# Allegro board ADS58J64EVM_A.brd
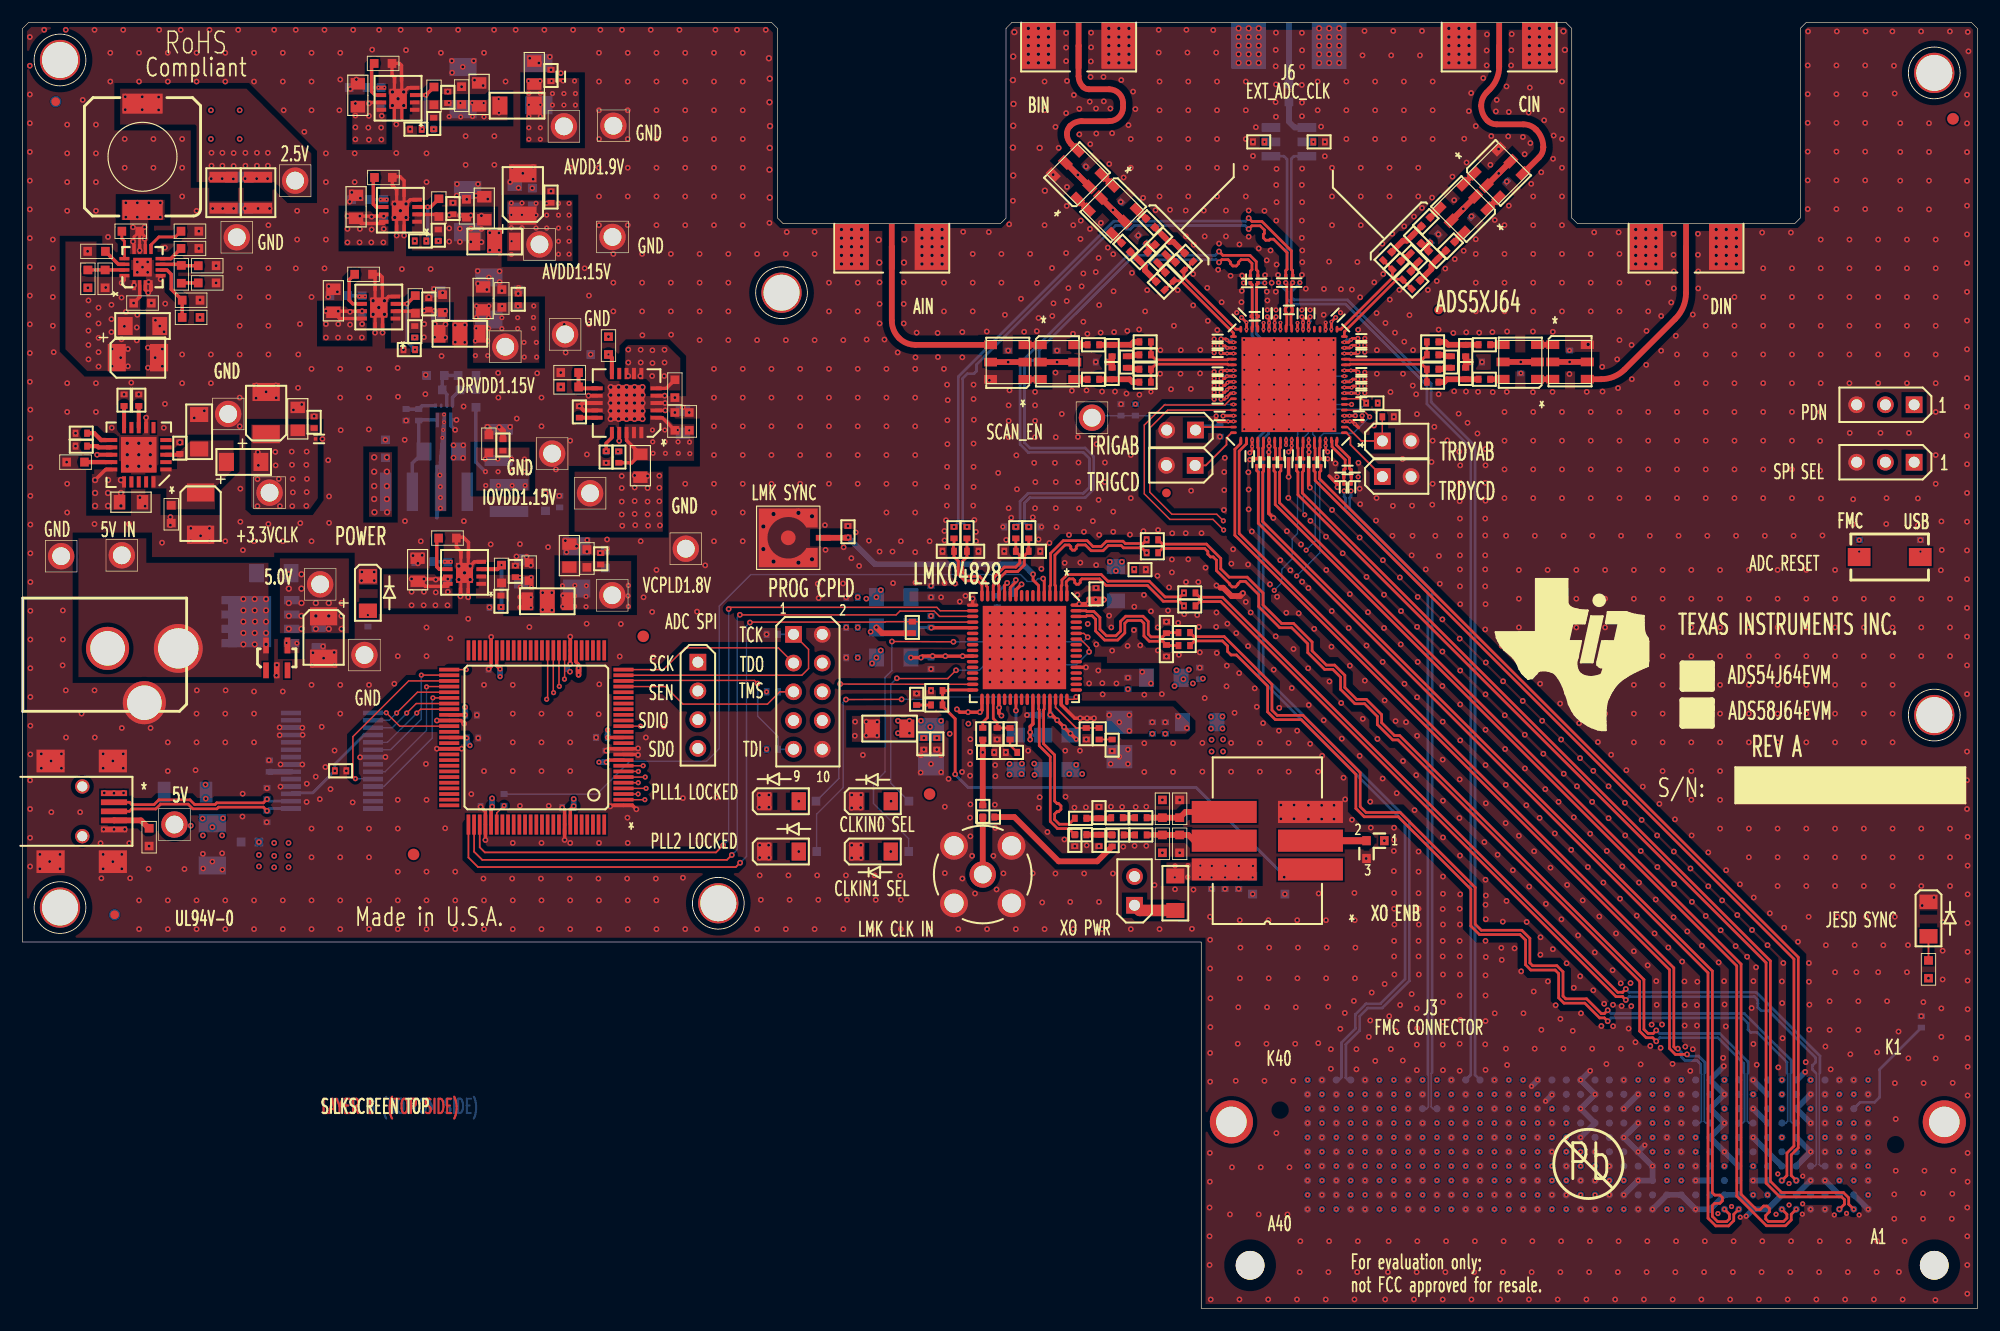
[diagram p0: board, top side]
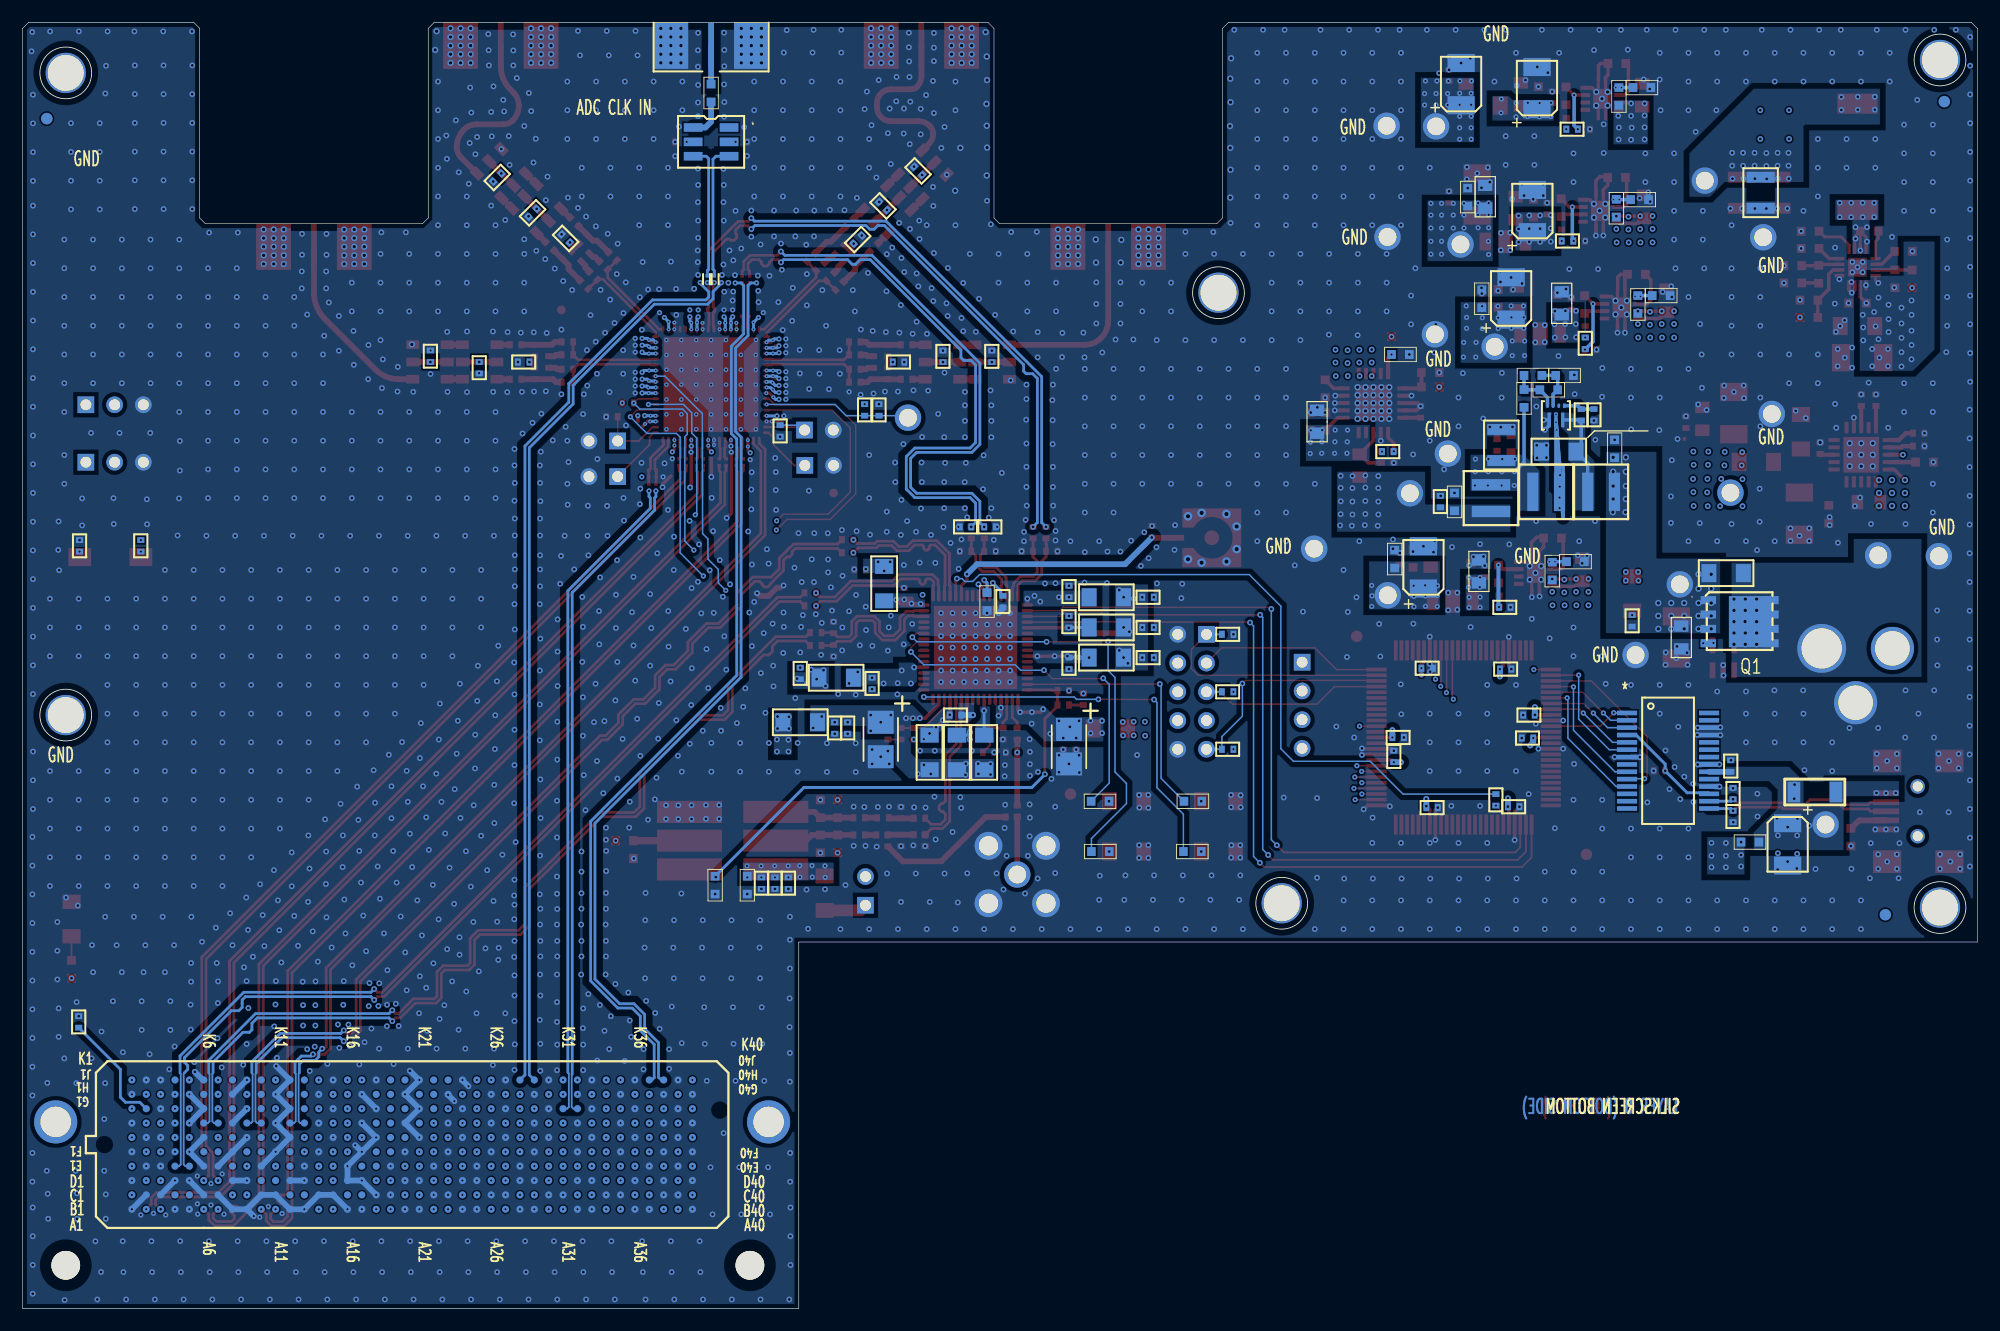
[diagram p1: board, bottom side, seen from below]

Outline 172.72 x 113.66 mm; copper layers: TOP, L2-GND1, L3-PWR1, L4-GND2, L5-GND3, L6-PWR2, L7-GND4, BOTTOM. Coordinates in mm from the lower left corner of the outline.
Outline path: 0,113.16 0.51,113.66 66.19,113.66 66.7,113.16 66.7,96.39 67.21,95.89 86.39,95.89 86.89,96.39 86.89,113.16 87.4,113.66 136.37,113.66 136.88,113.16 136.88,96.39 137.39,95.89 156.57,95.89 157.07,96.39 157.07,113.16 157.58,113.66 172.21,113.66 172.72,113.16 172.72,0 104.14,0 104.14,32.39 0,32.39 0,113.16

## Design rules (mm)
net group ACLK: nets ACLKN ACLKP
net group DIFFPAIR5: nets ACLK_N ACLK_P
net group DIFFPAIR10: nets DDINM DDINP
net group DIFFPAIR20: nets CLKM CLKP
net group DIFFPAIR44: nets SYSREF+ SYSREF-
net group DIFFPAIR45: nets SYSREFM SYSREFP
net group DIFFPAIR56: nets JESD_SYSREFM JESD_SYSREFP
net group DIFFPAIR57: nets JESD_CLKM JESD_CLKP
net group DIFFPAIR58: nets CLK_LAO_0M CLK_LAO_0P
net group DIFFPAIR60: nets OSCIN_N OSCIN_P
net group DIFFPAIR74: nets SYSREF_N SYSREF_P
net group DIFFPAIR77: nets FMC_SYSREF_N FMC_SYSREF_P
net group DIFFPAIR78: nets FPGA_JESD_SYSREFM FPGA_JESD_SYSREFP
net group DIFFPAIR79: nets FPGA_JESD_CLKM FPGA_JESD_CLKP
net group DIFFPAIR80: nets FMC_CLK_N FMC_CLK_P
net group DIFFPAIR81: nets CLKIN1N CLKIN1P
net group DIFFPAIR82: nets CLK_N CLK_P
net group DIFFPAIR83: nets CLKLA_0N CLKLA_0P
net group DIFFPAIR84: nets DAM DAP
net group DIFFPAIR85: nets DBM DBP
net group DIFFPAIR86: nets DB_M DB_P
net group DIFFPAIR87: nets DCM DCP
net group DIFFPAIR88: nets DC_M DC_P
net group DIFFPAIR89: nets DDM DDP
net group DIFFPAIR90: nets SYNCBABM SYNCBABP
net group DIFFPAIR91: nets SYNCBCDM SYNCBCDP
net group DIFFPAIR92: nets DD_M DD_P
net group DP1: nets BBINM BBINP
net group DP2: nets CCINM CCINP
net group DP5: nets DA_M DA_P
net group DP6: nets N18153199 N18153268
net group DP7: nets N19895674 N19895681

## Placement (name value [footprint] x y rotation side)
C2  .1uF  [0402]  95.33 83.66 180 bottom
C3  3.3pF  [0402]  97.54 83.66 90 top
C4  .1uF  [0402]  87.08 84.16 270 bottom
C5  .1uF  [0402]  91.4 84.16 270 bottom
C8  .1uF  [0402]  128.45 83.66 0 bottom
C9  3.3pF  [0402]  126.24 83.66 270 top
C10  .1uF  [0402]  136.69 84.18 270 bottom
C11  .1uF  [0402]  132.37 83.16 90 bottom
C16  .1uF  [0201]  118.29 80.92 0 top
C17  .1uF  [0201]  105.59 80.37 180 top
C18  .1uF  [0201]  105.77 78.89 180 top
C19  .1uF  [0201]  115.32 75.41 270 top
C20  .1uF  [0201]  118.29 85.75 0 top
C21  .1uF  [0201]  118.29 84.53 0 top
C22  .1uF  [0201]  111.86 75.41 270 top
C23  .1uF  [0201]  118.29 85.14 0 top
C24  .1uF  [0201]  118.29 82.14 0 top
C25  .01uF  [0201]  113.77 87.96 90 top
C26  .01uF  [0201]  109.98 87.96 90 top
C27  .1uF  [0201]  109.04 74.8 270 top
C28  .1uF  [0201]  109.65 74.8 270 top
C29  .1uF  [0201]  110.57 74.8 270 top
C30  .1uF  [0201]  111.18 74.8 270 top
C31  .1uF  [0201]  113.18 74.8 270 top
C32  .1uF  [0201]  112.57 74.8 270 top
C33  .1uF  [0201]  114.71 74.8 270 top
C34  .1uF  [0201]  114.1 74.8 270 top
C35  .1uF  [0201]  118.29 81.53 0 top
C36  .1uF  [0201]  113.03 87.96 90 top
C37  .1uF  [0201]  116.23 87.81 45 top
C38  .1uF  [0201]  110.74 87.96 90 top
C39  .1uF  [0201]  105.59 84.48 180 top
C40  .1uF  [0201]  107.49 87.81 135 top
C41  .1uF  [0201]  105.59 80.98 180 top
C43  .01uF  [0603]  111.89 107.44 270 bottom
C47  .1uF  [0201]  112.22 90.98 90 top
C48  .1uF  [0201]  111.61 90.98 90 top
C49  .1uF  [0402]  114.55 103.12 0 top
C50  1uF  [0402]  79.63 49.91 270 top
C51  10uF  [3528]  80.26 49.66 270 bottom
C52  .01uF  [0402]  80.77 49.91 270 top
C53  .1uF  [0201]  118.06 78.92 0 top
C56  .01uF  [0402]  98.73 65.3 0 top
C57  1uF  [0402]  99.82 51.31 270 bottom
C58  10uF  [3528]  96.9 50.29 270 bottom
C59  .01uF  [0402]  100.96 51.31 270 bottom
C60  .1uF  [0402]  80.77 54.61 180 top
C61  .01uF  [0402]  104.01 56.13 90 bottom
C62  .01uF  [0402]  73.28 60.2 180 bottom
C63  .01uF  [0402]  73.28 57.53 180 bottom
C64  .01uF  [0402]  73.28 62.87 180 bottom
C65  .68uF  [0402]  80.77 53.34 180 top
C66  3900pF  [0402]  95.12 50.8 270 top
C67  .1uF  [0402]  103.12 62.1 0 top
C68  .1uF  [0402]  103.12 63.25 0 top
C69  47pF  [0402]  93.98 50.8 270 top
C70  .1uF  [0402]  83.44 68.58 90 top
C71  .1uF  [0402]  82.3 68.58 90 top
C72  .1uF  [0402]  87.76 68.58 90 top
C73  .1uF  [0402]  88.9 68.58 90 top
C74  47uF  [1206]  15.6 77.5 90 top
C75  33uF  [TANT_B]  21.51 79.15 90 top
C76  4.7uF  [TANT_B]  15.72 70.26 270 top
C77  .1uF  [0402]  25.76 78.33 90 top
C78  .01uF  [0201]  26.19 76.86 0 top
C79  .1uF  [0402]  86.11 50.8 90 top
C80  .1uF  [0402]  96.7 43.38 180 top
C81  100pF  [0603]  108.69 37.41 90 bottom
C82  .1uF  [0402]  93.48 43.32 180 top
C83  10uF  [0805]  24.31 78.64 90 top
C84  2200pF  [0402]  107.44 37.59 90 bottom
C85  10pF  [0402]  105.05 37.59 90 bottom
C86  .1uF  [0402]  102.64 58.6 180 top
C87  10uF  [0603]  87.5 62.48 270 bottom
C88  .1uF  [0402]  86.11 62.48 270 bottom
C89  .1uF  [0402]  102.64 59.74 180 top
C90  .1uF  [0402]  106.25 37.59 90 bottom
C91  .1uF  [0402]  21.79 47.95 90 bottom
C92  .1uF  [0402]  93.48 41.87 180 top
C93  47pF  [0402]  21.59 43.48 270 bottom
C94  100pF  [0603]  111.53 37.41 90 bottom
C95  47pF  [0402]  21.59 45.52 90 bottom
C96  22uF  [1210]  19.15 98.63 90 bottom
C97  22uF  [1210]  17.75 98.63 90 top
C98  1uF  [0603]  4.67 74.81 180 top
C99  .1uF  [0402]  28.09 47.52 0 top
C100  1uF  [0402]  94.84 63.17 90 top
C101  1uF  [0402]  97.66 55.25 270 bottom
C102  1uF  [0402]  80.26 57.02 270 bottom
C103  47uF  [TANT_B]  26.59 59.31 270 top
C104  10uF  [0805]  26.16 59.31 270 bottom
C105  10uF  [0805]  29.62 107.24 90 top
C106  .47uF  [0603]  36.35 107.19 90 top
C107  .1uF  [0402]  37.57 107.06 90 top
C108  1uF  [0603]  38.79 107.21 90 top
C109  10uF  [0805]  40.34 107.31 90 top
C110  33uF  [TANT_B]  45.62 108.23 90 bottom
C111  10uF  [0805]  45.21 109.25 90 top
C112  .1uF  [0402]  46.69 108.99 90 top
C113  .01uF  [0201]  47.55 108.89 90 top
C114  .47uF  [0603]  31.85 110.06 0 top
C115  1.0uF  [0603]  57.63 78.41 90 top
C116  .01uF  [0603]  58.9 78.41 90 top
C117  10uF  [0805]  58.34 78.38 90 bottom
C118  10uF  [1206]  10.59 86.84 0 top
C119  4.7uF  [TANT_B]  10.19 84.05 0 top
C120  .1uF  [0603]  10.59 88.87 0 top
C121  .1uF  [0402]  92.97 41.37 90 top
C122  .1uF  [0402]  84.84 50.8 90 top
C123  4.7uF  [TANT_B]  39.32 97 90 bottom
C124  .1uF  [0603]  9.56 95.22 180 top
C125  22uF  [1210]  20.8 98.63 90 top
C126  10uF  [0805]  29.46 97.38 90 top
C127  .1uF  [0402]  38.02 97.23 90 top
C128  1uF  [0603]  39.22 97.26 90 top
C129  .47uF  [0603]  36.78 97.31 90 top
C130  33uF  [TANT_B]  44.2 98.48 90 top
C131  10uF  [0805]  43.48 98.27 90 bottom
C132  1uF  [0603]  45.03 98.25 90 bottom
C133  .1uF  [0402]  46.69 98.25 90 top
C134  .47uF  [0603]  31.88 99.97 0 top
C135  3300pF  [0603]  16.31 92.18 0 top
C136  .01uF  [0603]  14.78 95.22 0 top
C137  .47uF  [0603]  34.7 88.75 90 top
C138  .1uF  [0402]  35.89 88.8 90 top
C139  1uF  [0603]  37.11 88.82 90 top
C140  .1uF  [0402]  94.61 85.18 0 top
C141  .1uF  [0402]  94.61 82.13 0 top
C142  33uF  [TANT_B]  41.2 89.28 90 bottom
C143  10uF  [0805]  40.69 89.28 90 top
C144  3300pF  [0603]  16.31 90.65 0 top
C145  1uF  [0603]  43.79 89.26 90 bottom
C146  .1uF  [0402]  43.79 89.2 90 top
C147  1uF  [0603]  42.34 89.28 90 top
C148  4.7uF  [TANT_B]  38.91 107.87 90 bottom
C149  10uF  [0805]  9.58 71.27 0 top
C150  .1uF  [0402]  13.89 76.05 90 top
C151  1uF  [0603]  13.13 70.21 270 top
C152  .1uF  [0402]  40.97 44.35 0 bottom
C153  .1uF  [0402]  48.18 44.27 0 bottom
C154  .1uF  [0402]  39.62 52.45 180 bottom
C155  .1uF  [0402]  51.18 50.47 0 bottom
C156  .1uF  [0402]  51.56 48.79 270 bottom
C157  .1uF  [0402]  129.16 82.14 180 top
C158  .1uF  [0402]  129.16 85.19 180 top
C160  .1uF  [0201]  105.59 85.09 180 top
C161  .1uF  [0201]  105.59 81.58 180 top
C162  .1uF  [0402]  39.75 50.42 180 bottom
C163  4.7uF  [TANT_B]  16.76 41.02 270 bottom
C164  1uF  [0402]  90.3 52.45 180 bottom
C165  .1uF  [0402]  48.62 56.59 0 bottom
C166  .1uF  [0402]  41.68 56.52 0 bottom
C169  .1uF  [0402]  96.77 41.85 180 top
C170  .1uF  [0201]  108.43 75.33 270 top
C171  .1uF  [0201]  105.59 85.7 180 top
C172  .1uF  [0201]  118.29 82.75 0 top
C173  1uF  [0402]  80.26 60.71 90 bottom
C174  1uF  [0402]  80.26 63.37 90 bottom
C175  .1uF  [0402]  87.25 50.8 90 top
C182  10uF  [0805]  36.73 88.85 90 bottom
C183  .47uF  [0603]  30.12 91.41 0 top
C184  1.0uF  [0603]  50.98 84.33 180 bottom
C185  10uF  [0603]  57.63 81.31 270 top
C190  .1uF  [0201]  109.45 90.65 180 top
C191  .1uF  [0201]  108.18 90.65 0 top
C192  .1uF  [0201]  112.55 90.68 180 top
C193  .1uF  [0201]  111.28 90.68 0 top
C194  DNI  [0603]  32.05 76 90 bottom
C195  10uF  [1206]  36.98 75.74 0 bottom
C196  DNI  [0603]  37.87 81.2 180 bottom
C197  DNI  [0603]  41.2 76.43 90 top
C198  DNI  [0402]  42.44 76.33 90 top
C200  .1uF  [0402]  96.7 97.46 225 bottom
C201  .1uF  [0402]  98.93 94.49 135 bottom
C202  .1uF  [0402]  126.15 93.9 225 top
C203  .1uF  [0402]  123.99 96.06 225 top
C204  .1uF  [0402]  130.78 99.97 135 bottom
C205  .1uF  [0402]  127.66 96.85 135 bottom
C206  .1uF  [0402]  124.74 94.59 45 bottom
C207  3.3pF  [0402]  123 92.91 315 top
C263  10uF  [0805]  40.79 97.26 90 top
C265  .015uF  [0402]  49.2 79.25 90 top
C271  150uF  [1210]  42.06 76.33 90 bottom
C272  DNI  [0603]  46.2 71.3 90 bottom
C273  DNI  [0402]  47.45 71.32 90 bottom
C274  .1uF  [0402]  97.49 93.8 315 top
C275  .1uF  [0402]  99.65 95.95 315 top
C276  3.3pF  [0402]  100.64 92.81 45 top
C277  .1uF  [0402]  93.6 100.56 225 bottom
C278  10uF  [0805]  48.31 66.55 90 top
C279  33uF  [TANT_B]  48.95 65.51 90 bottom
C280  .1uF  [0402]  51.08 66.27 90 top
C281  1uF  [0603]  49.86 66.29 90 top
C282  1uF  [0603]  51.49 66.24 90 bottom
C283  .1uF  [0402]  43.54 65.15 90 top
C284  1uF  [0603]  44.75 65.13 90 top
C285  10uF  [0805]  44.04 65.15 90 bottom
C286  .47uF  [0603]  37.54 68.1 0 top
C287  .47uF  [0603]  42.32 64.92 90 top
C288  10uF  [0805]  27.46 89.08 90 top
C289  10uF  [0805]  34.9 65.3 90 top
C290  .1uF  [0402]  109.22 103.12 180 top
C291  .1uF  [0201]  105.59 82.19 180 top
C292  .1uF  [0201]  105.59 82.8 180 top
D1  LED GREEN  [LED_1206]  168.4 34.42 90 top
D2  LED GREEN  [LED_1206]  30.51 63.2 90 top
D3  LED GREEN  [LED_1206]  67.06 40.39 180 top
D4  LED GREEN  [LED_1206]  75.18 44.83 180 top
D5  LED GREEN  [LED_1206]  75.18 40.39 180 top
D6  LED GREEN  [LED_1206]  67.06 44.83 180 top
F1  FUSE 10A 63V FAST  [1206]  22.2 65 0 bottom
FB1  120 OHM @ 100MHz  [1206]  76.61 51.26 0 top
FB2  120 OHM @ 100MHz  [1206]  104.01 51.82 180 bottom
FB3  120 OHM @ 100MHz  [1206]  87.76 49.15 90 bottom
FB4  120 OHM @ 100MHz  [1206]  92.58 49.15 90 bottom
FB5  120 OHM @ 100MHz  [1206]  76.96 62.87 0 bottom
FB6  120 OHM @ 100MHz  [1206]  76.96 60.2 0 bottom
FB7  120 OHM @ 100MHz  [1206]  76.96 57.53 0 bottom
FB8  120 OHM @ 100MHz  [1206]  100.84 55.75 180 bottom
FB9  120 OHM @ 100MHz  [1206]  96.6 64.07 270 bottom
FB10  1K OHM @ 100MHz  [1806]  14.35 45.64 180 bottom
FB11  120 OHM @ 100MHz  [1206]  90.17 49.15 90 bottom
FB12  120 OHM @ 100MHz  [1206]  101.85 36.7 270 top
FB13  27uF  [1206_BEAD_NFM31P]  41.71 94.31 0 top
FB14  27uF  [1206_BEAD_NFM31P]  38.63 86.16 0 top
FB15  120 OHM @ 100MHz  [1206]  43.69 106.32 0 top
FB16  120 OHM @ 100MHz  [1206]  19.53 74.83 0 top
FB17  27uF  [1206_BEAD_NFM31P]  46.36 62.51 0 top
J1  CONN, SMA, JACK, 50 OHM, EDGE MNT  [SMA_SMEL_DUAL_PSF-S01_250X215]  76.8 95.89 0 top
J3  CON, SMVT, FIELD ARRAY, 400POS, MALE  [CON_SMVT_40X10_SEAM_MTG]  138.3 14.48 0 bottom
J5  CONN, SMA, JACK, 50 OHM, EDGE MNT  [SMA_SMEL_DUAL_PSF-S01_250X215]  146.98 95.89 0 top
J6  CONN, SMA, JACK, 50 OHM, EDGE MNT  [SMA_SMEL_DUAL_PSF-S01_250X215]  111.89 113.66 180 bottom
J10  CONN, SMP, PLUG, 50 OHM, THVT  [SMP_B120]  67.65 68.12 90 top
J12  CONN, SMA, JACK, 50 OHM, THVT  [SMA_THVT_312X312]  84.84 38.35 180 top
J13  CONN, USB MINI AB, SMT  [CON_SMRT_USBMNE20_F]  4.62 43.94 0 top
J14  CONN, JACK, PWR, MINI, R/A, TH  [CON_RAPC722_JACK_THVT_3]  10.63 58.34 270 top
J15  HDR, THVT, HI-TEMP, 5POS  [HDR_THVT_2X5_100_M]  68.12 59.59 0 top
J17  CONN, SMA, JACK, 50 OHM, EDGE MNT  [SMA_SMEL_DUAL_PSF-S01_250X215]  93.31 113.66 0 top
J18  CONN, SMA, JACK, 50 OHM, EDGE MNT  [SMA_SMEL_DUAL_PSF-S01_250X215]  130.47 113.66 0 top
J21  HMTSW-102-07-G-S-.240  [HDR_THVT_1X2_100_M]  103.61 74.52 270 top
J22  HMTSW-102-07-G-S-.240  [HDR_THVT_1X2_100_M]  120.14 73.53 90 top
J23  HMTSW-102-07-G-S-.240  [HDR_THVT_1X2_100_M]  103.63 77.65 270 top
J24  HMTSW-102-07-G-S-.240  [HDR_THVT_1X2_100_M]  120.14 76.68 90 top
J25  HMTSW-104-07-G-S-.240  [HDR_THVT_1X4_100_M]  59.66 57.12 0 top
JP2  HDR, THVT, 2POS  [HDR_THVT_1X2_100_M]  98.25 35.64 180 top
JP3  HDR, THVT, 3POS  [HDR_THVT_1X3_100_M]  167.13 74.8 270 top
JP7  HDR, THVT, 3POS  [HDR_THVT_1X3_100_M]  167.13 79.88 270 top
L1  1.5uH  [IND_SM_MSS1048]  10.59 101.8 0 top
L2  0 OHM  [IND_SM_169X169_XFL4020]  33.25 72.19 0 bottom
L3  0 OHM  [IND_SM_169X169_XFL4020]  42.98 71.63 270 bottom
L4  1.0uH  [IND_SM_169X169_XFL4020]  38.1 72.19 0 bottom
MT1  STANDOFF, FEMALE, 4-40 X 1 3/16", AL  [MFG125_PLATED]  61.47 35.81 0 top
MT2  STANDOFF, FEMALE, 4-40 X 1 3/16", AL  [MFG125_PLATED]  67.06 89.79 0 top
MT3  STANDOFF, FEMALE, 4-40 X 1 3/16", AL  [MFG125_PLATED]  3.3 35.43 0 top
MT4  STANDOFF, FEMALE, 4-40 X 1 3/16", AL  [MFG125_PLATED]  168.91 109.22 0 top
MT5  STANDOFF, FEMALE, 4-40 X 1 3/16", AL  [MFG125_PLATED]  168.91 52.45 0 top
MT6  STANDOFF, FEMALE, 4-40 X 1 3/16", AL  [MFG125_PLATED]  3.3 110.36 0 top
NOREF  -  []  -98.16 -130.05 0 top
NOREF#2  -  []  123 169.4 0 top
NOREF#3  -  []  136.32 11.5 0 top
NOREF#4  -  []  104.14 0 0 top
NOREF#5  -  [unnamed#2]  108.46 3.81 0 top
NOREF#6  -  [unnamed#2]  101.07 72.09 0 top
NOREF#7  -  [unnamed#2]  168.91 3.81 0 top
NOREF#8  -  []  0 113.16 0 top
NOREF#9  -  [unnamed#3]  54.84 59.41 0 top
NOREF#10  -  []  0 32.39 0 top
NOREF#11  -  []  86.89 113.16 0 top
NOREF#12  -  []  -0.51 40.89 0 top
NOREF#13  -  [unnamed#3]  80.14 45.47 270 top
NOREF#14  -  []  104.14 0 90 top
NOREF#15  -  []  138.2 58.34 0 top
NOREF#16  -  [unnamed#3]  34.54 40.13 0 top
NOREF#17  -  []  117.25 3.53 0 top
NOREF#18  -  [unnamed#2]  125.12 88.27 0 top
NOREF#19  -  [unnamed#2]  2.92 106.68 0 top
NOREF#20  -  []  98.29 17.8 0 top
NOREF#21  -  []  423.16 122.94 0 top
NOREF#22  -  [unnamed#2]  8.13 34.8 0 top
NOREF#23  -  []  104.14 0 90 top
NOREF#24  -  []  157.07 113.16 0 top
NOREF#25  -  []  66.7 113.16 0 top
NOREF#26  -  []  147.95 58.73 0 top
NOREF#27  -  []  29.26 33.88 0 top
NOREF#28  -  []  -97.92 -130.3 0 top
NOREF#29  -  []  0 32.39 90 top
NOREF#30  -  []  136.88 113.16 0 top
NOREF#31  -  [unnamed#3]  170.56 105.16 0 top
NOREF#32  -  []  0 32.39 0 top
NOREF#33  -  []  26.92 108.59 0 top
NOREF#34  -  []  146.48 49.43 0 top
NOREF#35  -  [unnamed#3]  8.13 34.8 180 bottom
NOREF#36  -  [unnamed#3]  2.92 106.68 180 bottom
NOREF#37  -  [unnamed#3]  170.59 105.18 180 bottom
Q1  CSD18532Q5  [SON_Q5B_8]  21.01 60.71 180 bottom
R2  4.99  [0402]  99.19 81.88 0 top
R3  24.9  [0402]  96.27 82.64 90 top
R5  24.9  [0402]  96.27 84.68 90 top
R6  4.99  [0402]  99.19 85.44 0 top
R8  4.99  [0402]  124.59 85.44 180 top
R9  24.9  [0402]  127.51 84.68 270 top
R11  24.9  [0402]  127.51 82.64 270 top
R12  4.99  [0402]  124.59 81.88 180 top
R13  0  [0603]  11.18 41.66 90 top
R18  1K  [0402]  162.28 67.41 270 bottom
R19  0  [0402]  98.32 79.43 270 bottom
R20  10K  [0402]  97.05 79.43 90 bottom
R21  240  [0402]  83.95 66.93 0 top
R23  1K  [0402]  119.23 80.04 180 top
R28  0  [0402]  35 78.99 90 bottom
R29  0  [0402]  33.88 78.99 270 bottom
R30  0  [0201]  109.14 90.96 270 top
R31  0  [0201]  108.48 90.96 270 top
R32  162K  [0603]  36.47 82.47 180 bottom
R33  10  [0603]  40.06 80.44 90 bottom
R34  100  [0201]  111.89 88.27 180 top
R35  0  [0201]  112.22 90.98 270 bottom
R36  10K  [0402]  167.69 67.41 90 bottom
R37  80.6K  [0603]  39.27 82.47 180 bottom
R39  0  [0201]  111.61 90.98 270 bottom
R40  240  [0402]  81.79 66.93 180 top
R41  1k  [0402]  30.51 60.78 90 bottom
R43  240  [0402]  89.41 66.93 0 top
R44  240  [0402]  87.25 66.93 180 top
R45  13.7k  [0402]  36.32 104.75 270 top
R47  200  [0402]  35.81 104.24 180 bottom
R48  10k  [0402]  34.75 104.24 180 top
R50  3.9k  [0402]  36.73 94.87 270 top
R51  665k  [0603]  14.78 93.7 0 top
R52  7.68k  [0603]  14.02 91.41 270 top
R57  1K  [0402]  66.24 59.59 180 bottom
R59  49.9  [0402]  72.92 68.66 90 top
R60  0  [0402]  85.34 43.43 0 top
R61  0  [0402]  96.27 41.34 90 top
R62  0  [0402]  84.84 43.94 90 top
R63  24.9  [0402]  99.19 84.3 180 top
R64  2k  [0402]  52.68 75.26 90 top
R65  620  [0402]  96.27 49.78 270 top
R66  39K  [0402]  78.99 53.85 90 top
R71  100  [0402]  98.81 43.38 180 top
R72  0  [0402]  5.18 76.23 0 top
R73  130  [0603]  100.71 44.16 270 top
R74  82  [0603]  102.23 44.16 90 top
R75  0  [0402]  5.18 77.37 0 top
R76  0  [0402]  8.96 80.29 270 top
R77  49.9  [0402]  95.11 43.83 90 top
R78  130  [0603]  100.71 41.07 90 top
R79  240  [0402]  101.07 58.14 270 top
R80  240  [0402]  101.07 60.2 90 top
R81  750  [0603]  77.52 44.83 0 bottom
R82  750  [0603]  77.5 40.39 0 bottom
R83  0  [0402]  10.26 80.29 270 top
R84  0  [0402]  167.77 25.32 90 bottom
R85  750  [0603]  69.32 44.83 0 bottom
R86  750  [0603]  69.37 40.39 0 bottom
R87  82  [0603]  102.23 41.07 270 top
R88  100  [0402]  98.81 41.85 180 top
R91  750  [0603]  168.4 29.97 270 top
R96  0  [0603]  20.09 41.22 180 bottom
R100  49.9  [0402]  85.34 49.15 0 top
R101  24.9  [0402]  99.19 83.03 0 top
R102  49.9  [0402]  95.11 41.37 270 top
R104  49.9  [0402]  87.38 49.15 180 top
R105  240  [0402]  87.25 69.09 180 bottom
R106  240  [0402]  89.41 69.09 0 bottom
R107  24.9  [0402]  124.59 83.03 0 top
R108  0  [0402]  99.82 67.94 0 top
R109  0  [0402]  99.82 66.8 0 top
R110  1K  [0402]  66.24 49.43 180 bottom
R111  10K  [0402]  66.24 54.51 180 bottom
R112  0  [0603]  7.29 91.01 90 top
R113  0  [0402]  42.55 44.96 90 bottom
R114  0  [0603]  5.77 91.01 270 top
R115  100k  [0603]  14.88 87.6 0 top
R116  10k  [0402]  35.15 94.36 180 top
R117  48.7k  [0603]  14.88 89.13 0 top
R118  100k  [0603]  6.53 93.45 180 top
R119  24.9  [0402]  124.59 84.3 180 top
R123  3.9k  [0402]  34.65 86.33 270 top
R124  10k  [0402]  34.16 84.76 180 top
R125  0  [0603]  30 88.75 90 bottom
R126  0  [0603]  27.94 89.53 180 bottom
R128  4.99K  [0402]  51.56 75.26 270 top
R129  0  [0805]  54.58 74.5 270 top
R133  100  [0201]  108.86 87.71 180 top
R134  10K  [0402]  78.61 60.2 90 top
R141  4.99  [0402]  103.06 92.9 315 top
R142  4.99  [0402]  100.55 90.39 315 top
R143  24.9  [0402]  100.46 94.43 45 top
R144  24.9  [0402]  99.02 92.99 45 top
R145  24.9  [0402]  102.25 92.09 135 top
R146  24.9  [0402]  101.36 91.2 315 top
R153  4.99  [0402]  123.09 90.49 225 top
R154  4.99  [0402]  120.58 93 225 top
R155  24.9  [0402]  123.18 94.53 315 top
R156  24.9  [0402]  124.62 93.09 315 top
R157  24.9  [0402]  122.28 91.29 45 top
R158  24.9  [0402]  121.39 92.19 225 top
R161  0  [0603]  31.9 97.26 90 bottom
R162  0  [0603]  29.84 98.02 180 bottom
R166  0  [0603]  48.34 81.46 0 top
R167  0  [0603]  48.34 82.73 180 top
R170  49.9  [0402]  105.79 77.57 270 bottom
R173  49.9  [0402]  120.65 78.82 0 top
R174  499  [0402]  36.22 94.36 180 bottom
R175  200  [0402]  52.1 75.74 180 bottom
R176  499  [0402]  34.65 85.32 270 bottom
R177  0  [0603]  37.57 65.18 90 bottom
R178  0  [0603]  35.51 66.01 180 bottom
R180  12.7k  [0402]  42.27 62.51 270 top
R181  10k  [0402]  41.76 61.98 180 bottom
R182  100  [0201]  117.07 74.12 0 top
R183  300  [0201]  117.7 73.51 0 top
R184  300  [0201]  116.43 73.51 0 top
R185  0  [0201]  116.76 72.57 270 top
R186  0  [0201]  117.37 72.57 270 top
R187  0  [0603]  51.77 85.12 270 top
R188  0  [0603]  31.67 107.14 90 bottom
R189  0  [0603]  29.64 107.92 180 bottom
SJP1  JUMPER_L_0603_SMT  [JUMPER_SMD_L_0603]  119.25 41.34 180 top
SW1  SWITCH, SMT, PUSHBUTTON  [SW_SMVT_SPST_EVQPJX_2]  164.97 66.42 0 top
T1  WBC1-1TL  [TFMR_6_150X150_60]  87.05 83.65 180 top
T2  WBC1-1TL  [TFMR_6_150X150_60]  91.44 83.65 0 top
T3  WBC1-1TL  [TFMR_6_150X150_60]  136.73 83.67 0 top
T4  WBC1-1TL  [TFMR_6_150X150_60]  132.33 83.67 180 top
T5  TCM2-33X+  [TFMR_6_160X150_50]  111.89 103.12 180 bottom
T6  WBC1-1TL  [TFMR_6_150X150_60]  93.21 100.23 135 top
T7  WBC1-1TL  [TFMR_6_150X150_60]  96.32 97.12 315 top
T8  WBC1-1TL  [TFMR_6_150X150_60]  130.42 100.33 45 top
T9  WBC1-1TL  [TFMR_6_150X150_60]  127.31 97.23 225 top
TP1  RED  [TESTPOINT_62DRILL_THM]  21.82 72.11 180 top
TP2  RED  [TESTPOINT_62DRILL_THM]  50.14 72.06 270 top
TP7  BLK  [TESTPOINT_62DRILL_THM]  30.2 57.76 0 top
TP8  BLK  [TESTPOINT_62DRILL_THM]  52.2 104.55 0 top
TP9  BLK  [TESTPOINT_62DRILL_THM]  18.92 94.69 0 top
TP10  BLK  [TESTPOINT_62DRILL_THM]  52.12 94.72 180 top
TP11  BLK  [TESTPOINT_62DRILL_THM]  47.93 86.11 0 top
TP14  RED  [TESTPOINT_62DRILL_THM]  42.65 85.01 0 top
TP15  RED  [TESTPOINT_62DRILL_THM]  45.67 94.06 0 top
TP16  RED  [TESTPOINT_62DRILL_THM]  26.29 64.01 0 top
TP18  RED  [TESTPOINT_62DRILL_THM]  24.08 99.69 0 top
TP19  RED  [TESTPOINT_62DRILL_THM]  47.83 104.5 0 top
TP20  WHT  [TESTPOINT_62DRILL_THM]  94.49 78.74 0 top
TP21  RED  [TESTPOINT_62DRILL_THM]  13.41 42.77 90 top
TP22  RED  [TESTPOINT_62DRILL_THM]  52.1 63.04 0 top
TP23  Testloop_Red  [TESTPOINT_62DIA]  8.76 66.57 0 top
TP24  Testloop_Black  [TESTPOINT_62DIA]  3.4 66.5 0 top
TP25  BLK  [TESTPOINT_62DRILL_THM]  58.6 67.16 0 top
TP26  BLK  [TESTPOINT_62DRILL_THM]  18.16 79.07 0 top
TP27  BLK  [TESTPOINT_62DRILL_THM]  46.79 75.56 0 top
U1  ADS5X6X  [QFN_72_10MMX10MM_0P50MM_PWRPAD]  111.89 81.66 180 top
U2  TPS7A8101  [SON_8_3MMX3MM_0P65MM]  31.47 88.48 180 top
U3  5M80ZT100  [TQFP_100_551X551_20]  45.39 50.47 180 top
U5  LMK04828  [QFN_64_360X360_0P50MM_PWRPAD]  88.52 58.42 270 top
U6  TPS7A4700  [QFN_20_199X199_0P65MM]  10.26 75.46 180 top
U7  FT245RL  [SSOP_28_413X220_26]  27.33 48.41 180 bottom
U8  TPS54319RTER  [QFN_16_124X124_PWRPAD]  10.59 92.05 90 top
U9  TPS74201  [QFN_20_197X197_0P65_RGW]  53.37 80.04 180 top
U10  TPS7A8101  [SON_8_3MMX3MM_0P65MM]  33.38 97.04 180 top
U11  TPS7A8101  [SON_8_3MMX3MM_0P65MM]  33.17 106.93 180 top
U12  TPS2400  [DBV5]  22.45 57.51 90 top
U15  TPS62085  [QFN_7_2MMX2MM]  37.24 78.94 270 bottom
U16  TPS7A8101  [SON_8_3MMX3MM_0P65MM]  39.04 65.02 180 top
Y1  122.88MHz  [VCXO_6_CUSTOM]  109.98 41.34 180 top

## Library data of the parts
C2 C8 C16-C24 C35-C41 C47 C48 C53 C160 C161 C170-C172 C190-C193 C201 C206 C291 C292 = CAP0402_0: tolerance: 10%
C3 C9 C207 C276 = CAP_0402_2pF
C4 C5 C10 C11 C49 C77 C107 C112 C127 C133 C138 C146 C150 C200 C204 C205 C277 C280 C283 C290 = CAP0603: tolerance: 10%
C25 C26 C78 C113 = CAP0402_0: tolerance: +/-10%
C27-C34 = CAP_0201_0.1uF: tolerance: 10%
C43 C66 = CAP NP_0: tolerance: 5%
C50 C52 C56 C57 C59 C61-C64 C67 C68 C70-C73 C79 C86 C88 C89 C121 C152-C156 C162 C165 C166 = CAPACITOR_NP_1: tolerance: 10%
C51 C58 = CAPACITOR POL_0: tolerance: 20%
C60 C65 C82 C91 C92 C98 C99 C108 C115 C117 C128 C139 C147 C151 C184 C282 C284 = CAP NP_0: tolerance: 10%
C69 = CAP NP_0: tolerance: 1%
C74 = CAP NP_0: tolerance: 20%
C75 C103 C110 C130 C142 C279 = CAP POL-B: tolerance: 10%
C76 C119 C123 C148 C163 = CAP_TANT_B_4.7uF_10V
C80 C90 C122 C169 C175 = CAP_0402_0.1uF_H: tolerance: 10%
C81 C94 = CAP_0603_100pF_H
C83 C111 C131 C143 C278 = CAP0201_0: tolerance: 20%
C84 = CAP_0402_2200pF_H
C85 = CAP_0402_10pF_H
C87 C265 = CAP NP_2: tolerance: 10%
C93 C95 = CAP0603: tolerance: 1%
C96 C97 C125 = CAP_1210_22uF: tolerance: 20%
C100-C102 C164 C173 C174 = CAP_0402_1uF
C104 C105 C109 C126 C132 C145 C149 C182 C263 C281 C285 C288 C289 = CAP NP_1: tolerance: 10%
C106 C114 C129 C134 C137 C183 C286 C287 = CAP_0603_.47uF
C116 = CAP_0603_0.01uF
C118 C195 = CAP_1206_2.2uF: tolerance: 10%
C120 C124 = CAP_0603_0.1uF: tolerance: 10%
C135 C144 C194 C196-C198 C272 C273 = CAP_0603_3300pF
C136 = CAP_0603_.01uF_25V_X7R_10%
C140 C141 C157 C158 C202 C203 C274 C275 = CAP_0603_0.1uF_H: tolerance: 10%
C185 = CAP_0603_2.2uF: tolerance: 10%
C271 = CAP_1210_150uF_6.3V: tolerance: 10%, 6.3V, X5R
D1 D3-D6 = LED
D2 = LED_GREEN_1206
F1 = FUSE_0
FB1-FB12 FB15 FB16 = FERRITE_BEAD_0402_H
FB13 FB14 FB17 = BEAD_NFM31P
J1 J5 J6 J17 J18 = SMA-END_PLUG_ROUND
J3 = CON_SMVT_40X10_ASP-134487-01
J10 = SMP_PLUG_SMT
J12 = SMA-THVT_142-0701-201_REC
J13 = USB_MINI_AB_MNE20-5G5P10
J14 = CONN JACK PWR
J15 = HEADER_2x5_100
J21-J24 = HEADER_1x2_100
J25 = HEADER_1x4_0
JP2 = SMD_JUMPER_1x2
JP3 = Jumper_1x3_100_0
JP7 = SMD_JUMPER_1x3
L1-L4 = INDUCTOR-1
MT1-MT6 = MOUNTING_HOLE
Q1 = CSD18532Q5B
R2 R6 R8 R12 R141 R142 R153 R154 = Res_0201_H: tolerance: 1%
R3 R5 R9 R11 R143 R144 R155 R156 = RES0603: tolerance: .1%
R13 R75 R76 R83 R113 = R: tolerance: 5%
R18 R20 R36 R65 R66 R134 = R_1: tolerance: 1%
R19 R60 R61 = Res_0402_Zero_DNI
R21 R40 R43 R44 R79 R80 R105 R106 = Res_0402_249
R23 = RES0603: tolerance: 1%
R28 R29 R96 R112 R114 R126 R162 R167 R178 R189 = Res_0603_Zero_DNI
R30 R31 R35 R39 R185 R186 = Res_0402_Zero_H_DNI
R32 = Res_0603_162K
R33 = Res_0603_10
R34 R133 R182 = Res_0201_200_H: tolerance: 1%
R37 = Res_0603_80.6K
R41 = Res_0402_1k: tolerance: 1%
R45 R47 R50 R123 R174-R176 R180 = Res_0603_12.4k
R48 R116 R117 R124 R181 = Res_0603_10k
R51 = Res_0603_665K
R52 = Res_0603_7.68K
R57 R110 R111 = R_0: tolerance: 1%
R59 R77 R100 R102 R104 R170 R173 = Res_0402_49.9: tolerance: 1%
R62 R108 R109 = Res_0402_Zero_H
R63 R84 R101 R107 R119 R145 R146 R157 R158 = Res_0402_Zero
R64 = Res_0603_634
R71 R88 = Res_0402_100_H
R72 = R: tolerance: 1%
R73 R74 R78 R87 = RESISTOR_0: tolerance: 1%
R81 R82 R85 R86 R91 = RESISTOR_0
R115 R118 = Res_0603_100k
R125 R129 R161 R166 R177 R187 R188 = Res_0603_Zero
R128 = Res_0603_4.99K
R183 R184 = Res_0201_200_H
SJP1 = JUMPER_SMD_L_0603
SW1 = SPST_EVQ-PJ
T1-T4 T6-T9 = XFMR_6_ADT2-1T+_2
T5 = TFMR_6_TCM2-33X+
TP1 TP14-TP16 TP18 TP19 TP21 TP22 = TESTPOINT_BLUE
TP2 = TESTPOINT_GRN
TP7-TP11 TP25-TP27 = TESTPOINT_BLK
TP20 = T POINT R
TP23 TP24 = TESTLOOP_BLACK
U1 = ADS58J66_2
U2 U10 U11 U16 = TPS7A8101
U3 = ALTERA_5M80ZT100
U5 = LMK04828_0
U6 = TPS7A4700
U7 = FT245RL
U8 = TPS54319RTE
U9 = TPS74201/QFN20
U12 = TPS2400
U15 = TPS62085
Y1 = OSC_SM_6_TCO-2100-SERIES_2

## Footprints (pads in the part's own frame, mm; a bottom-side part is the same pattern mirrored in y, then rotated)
0201
  rect 0.305x0.305 smd: 1(-0.305,0) 2(0.305,0)
0402
  rect 0.508x0.635 smd: 1(-0.508,0) 2(0.508,0)
0603
  rect 0.762x0.787 smd: 1(-0.787,0) 2(0.787,0)
0805
  rect 1.016x1.27 smd: 1(-1.016,0) 2(1.016,0)
1206
  rect 1.321x1.6 smd: 1(-1.524,0) 2(1.524,0)
1206_BEAD_NFM31P
  rect 1.016x1.575 smd: 1(-1.778,0) 3(1.778,0)
  rect 1.321x2.032 smd: 2(0,0)
1210
  rect 0.965x2.489 smd: 1(-1.372,0) 2(1.372,0)
1806
  rect 1.118x1.829 smd: 1(-1.854,0) 2(1.854,0)
3528
  rect 2.032x2.286 smd: 1(-1.524,0) 2(1.524,0)
CON_RAPC722_JACK_THVT_3
  round 4.318 hole 3.556: 1(0,3.124)
  round 3.81 hole 3.048: 2(0,-3.124) 3(4.801,0.127)
CON_SMRT_USBMNE20_F
  round 1.27 hole 0.889 unplated: (0.65,2.2) (0.65,-2.2)
  rect 2.311x0.508 smd: 1(3.45,1.6) 2(3.45,0.8) 3(3.45,0) 4(3.45,-0.8) 5(3.45,-1.6)
  rect 2.489x2.007 smd: 6(-2.15,-4.45) 7(3.35,-4.45) 8(3.35,4.45) 9(-2.15,4.45)
CON_SMVT_40X10_SEAM_MTG
  round 3.81 hole 2.692: (-31.496,-2.007) (31.496,-2.007)
  round 0 hole 1.27 unplated: (-27.191,-3.048) (27.191,0)
  round 0.635 smd: A1(24.765,5.715) A2(23.495,5.715) A3(22.225,5.715) A4(20.955,5.715) A5(19.685,5.715) A6(18.415,5.715) A7(17.145,5.715) A8(15.875,5.715) A9(14.605,5.715) A10(13.335,5.715) A11(12.065,5.715) A12(10.795,5.715) A13(9.525,5.715) A14(8.255,5.715) A15(6.985,5.715) A16(5.715,5.715) A17(4.445,5.715) A18(3.175,5.715) A19(1.905,5.715) A20(0.635,5.715) A21(-0.635,5.715) A22(-1.905,5.715) A23(-3.175,5.715) A24(-4.445,5.715) A25(-5.715,5.715) A26(-6.985,5.715) A27(-8.255,5.715) A28(-9.525,5.715) A29(-10.795,5.715) A30(-12.065,5.715) A31(-13.335,5.715) A32(-14.605,5.715) A33(-15.875,5.715) A34(-17.145,5.715) A35(-18.415,5.715) A36(-19.685,5.715) A37(-20.955,5.715) A38(-22.225,5.715) A39(-23.495,5.715) A40(-24.765,5.715) B1(24.765,4.445) B2(23.495,4.445) B3(22.225,4.445) B4(20.955,4.445) B5(19.685,4.445) B6(18.415,4.445) B7(17.145,4.445) B8(15.875,4.445) B9(14.605,4.445) B10(13.335,4.445) B11(12.065,4.445) B12(10.795,4.445) B13(9.525,4.445) B14(8.255,4.445) B15(6.985,4.445) B16(5.715,4.445) B17(4.445,4.445) B18(3.175,4.445) B19(1.905,4.445) B20(0.635,4.445) B21(-0.635,4.445) B22(-1.905,4.445) B23(-3.175,4.445) B24(-4.445,4.445) B25(-5.715,4.445) B26(-6.985,4.445) B27(-8.255,4.445) B28(-9.525,4.445) B29(-10.795,4.445) B30(-12.065,4.445) B31(-13.335,4.445) B32(-14.605,4.445) B33(-15.875,4.445) B34(-17.145,4.445) B35(-18.415,4.445) B36(-19.685,4.445) B37(-20.955,4.445) B38(-22.225,4.445) B39(-23.495,4.445) B40(-24.765,4.445) C1(24.765,3.175) C2(23.495,3.175) C3(22.225,3.175) C4(20.955,3.175) C5(19.685,3.175) C6(18.415,3.175) C7(17.145,3.175) C8(15.875,3.175) C9(14.605,3.175) C10(13.335,3.175) C11(12.065,3.175) C12(10.795,3.175) C13(9.525,3.175) C14(8.255,3.175) C15(6.985,3.175) C16(5.715,3.175) C17(4.445,3.175) C18(3.175,3.175) C19(1.905,3.175) C20(0.635,3.175) C21(-0.635,3.175) C22(-1.905,3.175) C23(-3.175,3.175) C24(-4.445,3.175) C25(-5.715,3.175) C26(-6.985,3.175) C27(-8.255,3.175) C28(-9.525,3.175) C29(-10.795,3.175) C30(-12.065,3.175) C31(-13.335,3.175) C32(-14.605,3.175) C33(-15.875,3.175) C34(-17.145,3.175) C35(-18.415,3.175) C36(-19.685,3.175) C37(-20.955,3.175) C38(-22.225,3.175) C39(-23.495,3.175) C40(-24.765,3.175) D1(24.765,1.905) D2(23.495,1.905) D3(22.225,1.905) D4(20.955,1.905) D5(19.685,1.905) D6(18.415,1.905) D7(17.145,1.905) D8(15.875,1.905) D9(14.605,1.905) D10(13.335,1.905) D11(12.065,1.905) D12(10.795,1.905) D13(9.525,1.905) D14(8.255,1.905) D15(6.985,1.905) D16(5.715,1.905) D17(4.445,1.905) D18(3.175,1.905) D19(1.905,1.905) D20(0.635,1.905) D21(-0.635,1.905) D22(-1.905,1.905) D23(-3.175,1.905) D24(-4.445,1.905) D25(-5.715,1.905) D26(-6.985,1.905) D27(-8.255,1.905) D28(-9.525,1.905) D29(-10.795,1.905) D30(-12.065,1.905) D31(-13.335,1.905) D32(-14.605,1.905) D33(-15.875,1.905) D34(-17.145,1.905) D35(-18.415,1.905) D36(-19.685,1.905) D37(-20.955,1.905) D38(-22.225,1.905) D39(-23.495,1.905) D40(-24.765,1.905) E1(24.765,0.635) E2(23.495,0.635) E3(22.225,0.635) E4(20.955,0.635) E5(19.685,0.635) E6(18.415,0.635) E7(17.145,0.635) E8(15.875,0.635) E9(14.605,0.635) E10(13.335,0.635) E11(12.065,0.635) E12(10.795,0.635) E13(9.525,0.635) E14(8.255,0.635) E15(6.985,0.635) E16(5.715,0.635) E17(4.445,0.635) E18(3.175,0.635) E19(1.905,0.635) E20(0.635,0.635) E21(-0.635,0.635) E22(-1.905,0.635) E23(-3.175,0.635) E24(-4.445,0.635) E25(-5.715,0.635) E26(-6.985,0.635) E27(-8.255,0.635) E28(-9.525,0.635) E29(-10.795,0.635) E30(-12.065,0.635) E31(-13.335,0.635) E32(-14.605,0.635) E33(-15.875,0.635) E34(-17.145,0.635) E35(-18.415,0.635) E36(-19.685,0.635) E37(-20.955,0.635) E38(-22.225,0.635) E39(-23.495,0.635) E40(-24.765,0.635) F1(24.765,-0.635) F2(23.495,-0.635) F3(22.225,-0.635) F4(20.955,-0.635) F5(19.685,-0.635) F6(18.415,-0.635) F7(17.145,-0.635) F8(15.875,-0.635) F9(14.605,-0.635) F10(13.335,-0.635) F11(12.065,-0.635) F12(10.795,-0.635) F13(9.525,-0.635) F14(8.255,-0.635) F15(6.985,-0.635) F16(5.715,-0.635) F17(4.445,-0.635) F18(3.175,-0.635) F19(1.905,-0.635) F20(0.635,-0.635) F21(-0.635,-0.635) F22(-1.905,-0.635) F23(-3.175,-0.635) F24(-4.445,-0.635) F25(-5.715,-0.635) F26(-6.985,-0.635) F27(-8.255,-0.635) F28(-9.525,-0.635) F29(-10.795,-0.635) F30(-12.065,-0.635) F31(-13.335,-0.635) F32(-14.605,-0.635) F33(-15.875,-0.635) F34(-17.145,-0.635) F35(-18.415,-0.635) F36(-19.685,-0.635) F37(-20.955,-0.635) F38(-22.225,-0.635) F39(-23.495,-0.635) F40(-24.765,-0.635) G1(24.765,-1.905) G2(23.495,-1.905) G3(22.225,-1.905) G4(20.955,-1.905) G5(19.685,-1.905) G6(18.415,-1.905) G7(17.145,-1.905) G8(15.875,-1.905) G9(14.605,-1.905) G10(13.335,-1.905) G11(12.065,-1.905) G12(10.795,-1.905) G13(9.525,-1.905) G14(8.255,-1.905) G15(6.985,-1.905) G16(5.715,-1.905) G17(4.445,-1.905) G18(3.175,-1.905) G19(1.905,-1.905) G20(0.635,-1.905) G21(-0.635,-1.905) G22(-1.905,-1.905) G23(-3.175,-1.905) G24(-4.445,-1.905) G25(-5.715,-1.905) G26(-6.985,-1.905) G27(-8.255,-1.905) G28(-9.525,-1.905) G29(-10.795,-1.905) G30(-12.065,-1.905) G31(-13.335,-1.905) G32(-14.605,-1.905) G33(-15.875,-1.905) G34(-17.145,-1.905) G35(-18.415,-1.905) G36(-19.685,-1.905) G37(-20.955,-1.905) G38(-22.225,-1.905) G39(-23.495,-1.905) G40(-24.765,-1.905) H1(24.765,-3.175) H2(23.495,-3.175) H3(22.225,-3.175) H4(20.955,-3.175) H5(19.685,-3.175) H6(18.415,-3.175) H7(17.145,-3.175) H8(15.875,-3.175) H9(14.605,-3.175) H10(13.335,-3.175) H11(12.065,-3.175) H12(10.795,-3.175) H13(9.525,-3.175) H14(8.255,-3.175) H15(6.985,-3.175) H16(5.715,-3.175) H17(4.445,-3.175) H18(3.175,-3.175) H19(1.905,-3.175) H20(0.635,-3.175) H21(-0.635,-3.175) H22(-1.905,-3.175) H23(-3.175,-3.175) H24(-4.445,-3.175) H25(-5.715,-3.175) H26(-6.985,-3.175) H27(-8.255,-3.175) H28(-9.525,-3.175) H29(-10.795,-3.175) H30(-12.065,-3.175) H31(-13.335,-3.175) H32(-14.605,-3.175) H33(-15.875,-3.175) H34(-17.145,-3.175) H35(-18.415,-3.175) H36(-19.685,-3.175) H37(-20.955,-3.175) H38(-22.225,-3.175) H39(-23.495,-3.175) H40(-24.765,-3.175) J1(24.765,-4.445) J2(23.495,-4.445) J3(22.225,-4.445) J4(20.955,-4.445) J5(19.685,-4.445) J6(18.415,-4.445) J7(17.145,-4.445) J8(15.875,-4.445) J9(14.605,-4.445) J10(13.335,-4.445) J11(12.065,-4.445) J12(10.795,-4.445) J13(9.525,-4.445) J14(8.255,-4.445) J15(6.985,-4.445) J16(5.715,-4.445) J17(4.445,-4.445) J18(3.175,-4.445) J19(1.905,-4.445) J20(0.635,-4.445) J21(-0.635,-4.445) J22(-1.905,-4.445) J23(-3.175,-4.445) J24(-4.445,-4.445) J25(-5.715,-4.445) J26(-6.985,-4.445) J27(-8.255,-4.445) J28(-9.525,-4.445) J29(-10.795,-4.445) J30(-12.065,-4.445) J31(-13.335,-4.445) J32(-14.605,-4.445) J33(-15.875,-4.445) J34(-17.145,-4.445) J35(-18.415,-4.445) J36(-19.685,-4.445) J37(-20.955,-4.445) J38(-22.225,-4.445) J39(-23.495,-4.445) J40(-24.765,-4.445) K1(24.765,-5.715) K2(23.495,-5.715) K3(22.225,-5.715) K4(20.955,-5.715) K5(19.685,-5.715) K6(18.415,-5.715) K7(17.145,-5.715) K8(15.875,-5.715) K9(14.605,-5.715) K10(13.335,-5.715) K11(12.065,-5.715) K12(10.795,-5.715) K13(9.525,-5.715) K14(8.255,-5.715) K15(6.985,-5.715) K16(5.715,-5.715) K17(4.445,-5.715) K18(3.175,-5.715) K19(1.905,-5.715) K20(0.635,-5.715) K21(-0.635,-5.715) K22(-1.905,-5.715) K23(-3.175,-5.715) K24(-4.445,-5.715) K25(-5.715,-5.715) K26(-6.985,-5.715) K27(-8.255,-5.715) K28(-9.525,-5.715) K29(-10.795,-5.715) K30(-12.065,-5.715) K31(-13.335,-5.715) K32(-14.605,-5.715) K33(-15.875,-5.715) K34(-17.145,-5.715) K35(-18.415,-5.715) K36(-19.685,-5.715) K37(-20.955,-5.715) K38(-22.225,-5.715) K39(-23.495,-5.715) K40(-24.765,-5.715)
DBV5
  rect 1.4x0.5 smd: 1(-1.1,0.95) 2(-1.1,0) 3(-1.1,-0.95) 4(1.1,-0.95) 5(1.1,0.95)
HDR_THVT_1X2_100_M
  rect 1.473x1.473 hole 0.965: 1(0,0)
  round 1.473 hole 0.965: 2(0,-2.54)
HDR_THVT_1X3_100_M
  rect 1.473x1.473 hole 0.965: 1(0,0)
  round 1.473 hole 0.965: 2(0,-2.54) 3(0,-5.08)
HDR_THVT_1X4_100_M
  rect 1.473x1.473 hole 0.965: 1(0,0)
  round 1.473 hole 0.965: 2(0,-2.54) 3(0,-5.08) 4(0,-7.62)
HDR_THVT_2X5_100_M
  rect 1.473x1.473 hole 0.965: 1(0,0)
  round 1.473 hole 0.965: 2(2.54,0) 3(0,-2.54) 4(2.54,-2.54) 5(0,-5.08) 6(2.54,-5.08) 7(0,-7.62) 8(2.54,-7.62) 9(0,-10.16) 10(2.54,-10.16)
IND_SM_169X169_XFL4020
  rect 0.991x3.404 smd: 1(-1.181,0) 2(1.181,0)
IND_SM_MSS1048
  rect 3.556x1.778 smd: 1(0,-4.699) 2(0,4.699)
JUMPER_SMD_L_0603
  rect 0.762x0.813 smd: 1(-1.067,0) 2(0.508,0) 3(0.508,1.575)
LED_1206
  rect 1.27x1.6 smd: 1(-1.524,0) 2(1.524,0)
MFG125_PLATED
  round 3.556 hole 3.175: 1(0,0)
QFN_7_2MMX2MM
  rect 0.4x0.25 smd: 1(-0.851,0.75)
  oval 0.4x0.25 smd: 2(-0.851,0.25) 3(-0.851,-0.25) 4(-0.851,-0.75)
  rect 1.3x0.3 smd: 5(0.401,-0.6) 6(0.401,0) 7(0.401,0.6)
QFN_16_124X124_PWRPAD
  rect 0.889x0.305 smd: 1(-1.6,0.749) 2(-1.6,0.249) 3(-1.6,-0.249) 4(-1.6,-0.749) 9(1.6,-0.749) 10(1.6,-0.249) 11(1.6,0.249) 12(1.6,0.749)
  rect 0.305x0.889 smd: 5(-0.749,-1.6) 6(-0.249,-1.6) 7(0.249,-1.6) 8(0.749,-1.6) 13(0.749,1.6) 14(0.249,1.6) 15(-0.249,1.6) 16(-0.749,1.6)
  rect 1.651x1.651 smd: 17(0,0)
QFN_20_197X197_0P65_RGW
  rect 1x0.35 smd: 1(-2.607,1.3) 2(-2.607,0.65) 3(-2.607,0) 4(-2.607,-0.65) 5(-2.607,-1.3) 11(2.607,-1.3) 12(2.607,-0.65) 13(2.607,0) 14(2.607,0.65) 15(2.607,1.3)
  rect 0.35x1 smd: 6(-1.3,-2.607) 7(-0.65,-2.607) 8(0,-2.607) 9(0.65,-2.607) 10(1.3,-2.607) 16(1.3,2.607) 17(0.65,2.607) 18(0,2.607) 19(-0.65,2.607) 20(-1.3,2.607)
  rect 3.15x3.15 smd: 21(0,0)
QFN_20_199X199_0P65MM
  rect 1x0.35 smd: 1(-2.4,1.3) 2(-2.4,0.65) 3(-2.4,0) 4(-2.4,-0.65) 5(-2.4,-1.3) 11(2.4,-1.3) 12(2.4,-0.65) 13(2.4,0) 14(2.4,0.65) 15(2.4,1.3)
  rect 0.35x1 smd: 6(-1.3,-2.4) 7(-0.65,-2.4) 8(0,-2.4) 9(0.65,-2.4) 10(1.3,-2.4) 16(1.3,2.4) 17(0.65,2.4) 18(0,2.4) 19(-0.65,2.4) 20(-1.3,2.4)
  rect 3.15x3.15 smd: 21(0,0)
QFN_64_360X360_0P50MM_PWRPAD
  oval 1.016x0.305 smd: 1(-4.58,3.753) 2(-4.58,3.252) 3(-4.58,2.752) 4(-4.58,2.252) 5(-4.58,1.751) 6(-4.58,1.251) 7(-4.58,0.751) 8(-4.58,0.25) 9(-4.58,-0.25) 10(-4.58,-0.751) 11(-4.58,-1.251) 12(-4.58,-1.751) 13(-4.58,-2.252) 14(-4.58,-2.752) 15(-4.58,-3.252) 16(-4.58,-3.753) 33(4.58,-3.753) 34(4.58,-3.252) 35(4.58,-2.752) 36(4.58,-2.252) 37(4.58,-1.751) 38(4.58,-1.251) 39(4.58,-0.751) 40(4.58,-0.25) 41(4.58,0.25) 42(4.58,0.751) 43(4.58,1.251) 44(4.58,1.751) 45(4.58,2.252) 46(4.58,2.752) 47(4.58,3.252) 48(4.58,3.753)
  oval 0.305x1.016 smd: 17(-3.753,-4.58) 18(-3.252,-4.58) 19(-2.752,-4.58) 20(-2.252,-4.58) 21(-1.751,-4.58) 22(-1.251,-4.58) 23(-0.751,-4.58) 24(-0.25,-4.58) 25(0.25,-4.58) 26(0.751,-4.58) 27(1.251,-4.58) 28(1.751,-4.58) 29(2.252,-4.58) 30(2.752,-4.58) 31(3.252,-4.58) 32(3.753,-4.58) 49(3.753,4.58) 50(3.252,4.58) 51(2.752,4.58) 52(2.252,4.58) 53(1.751,4.58) 54(1.251,4.58) 55(0.751,4.58) 56(0.25,4.58) 57(-0.25,4.58) 58(-0.751,4.58) 59(-1.251,4.58) 60(-1.751,4.58) 61(-2.252,4.58) 62(-2.752,4.58) 63(-3.252,4.58) 64(-3.753,4.58)
  rect 7.366x7.366 smd: 65(0,0)
QFN_72_10MMX10MM_0P50MM_PWRPAD
  oval 0.6x0.24 smd: 1(-4.9,4.25) 2(-4.9,3.75) 3(-4.9,3.25) 4(-4.9,2.75) 5(-4.9,2.25) 6(-4.9,1.75) 7(-4.9,1.25) 8(-4.9,0.75) 9(-4.9,0.25) 10(-4.9,-0.25) 11(-4.9,-0.75) 12(-4.9,-1.25) 13(-4.9,-1.75) 14(-4.9,-2.25) 15(-4.9,-2.75) 16(-4.9,-3.25) 17(-4.9,-3.75) 18(-4.9,-4.25) 37(4.9,-4.25) 38(4.9,-3.75) 39(4.9,-3.25) 40(4.9,-2.75) 41(4.9,-2.25) 42(4.9,-1.75) 43(4.9,-1.25) 44(4.9,-0.75) 45(4.9,-0.25) 46(4.9,0.25) 47(4.9,0.75) 48(4.9,1.25) 49(4.9,1.75) 50(4.9,2.25) 51(4.9,2.75) 52(4.9,3.25) 53(4.9,3.75) 54(4.9,4.25)
  oval 0.24x0.6 smd: 19(-4.25,-4.9) 20(-3.75,-4.9) 21(-3.25,-4.9) 22(-2.75,-4.9) 23(-2.25,-4.9) 24(-1.75,-4.9) 25(-1.25,-4.9) 26(-0.75,-4.9) 27(-0.25,-4.9) 28(0.25,-4.9) 29(0.75,-4.9) 30(1.25,-4.9) 31(1.75,-4.9) 32(2.25,-4.9) 33(2.75,-4.9) 34(3.25,-4.9) 35(3.75,-4.9) 36(4.25,-4.9) 55(4.25,4.9) 56(3.75,4.9) 57(3.25,4.9) 58(2.75,4.9) 59(2.25,4.9) 60(1.75,4.9) 61(1.25,4.9) 62(0.75,4.9) 63(0.25,4.9) 64(-0.25,4.9) 65(-0.75,4.9) 66(-1.25,4.9) 67(-1.75,4.9) 68(-2.25,4.9) 69(-2.75,4.9) 70(-3.25,4.9) 71(-3.75,4.9) 72(-4.25,4.9)
  rect 8.382x8.382 smd: 73(0,0)
SMA_SMEL_DUAL_PSF-S01_250X215
  rect 0.508x4.064 smd: 1(0,-2.032)
  rect 3.048x4.064 smd: 2(-3.556,-2.032) 3(3.556,-2.032) 4(-3.556,-2.032) 5(3.556,-2.032)
SMA_THVT_312X312
  round 2.337 hole 1.575: 1(0,0)
  round 2.464 hole 1.702: 2(-2.54,2.54) 3(2.54,2.54) 4(2.54,-2.54) 5(-2.54,-2.54)
SMP_B120
  rect 0.508x1.321 smd: 1(0,-3.1)
  custom 1.3x1.3 smd: 2(0,0)
SON_8_3MMX3MM_0P65MM
  rect 0.85x0.35 smd: 1(-1.475,0.975) 2(-1.475,0.325) 3(-1.475,-0.325) 4(-1.475,-0.975) 5(1.475,-0.975) 6(1.475,-0.325) 7(1.475,0.325) 8(1.475,0.975)
  rect 1.5x1.75 smd: 9(0,0)
SON_Q5B_8
  rect 1.372x0.711 smd: 1(-2.767,1.905) 2(-2.767,0.635) 3(-2.767,-0.635) 4(-2.767,-1.905) 5(2.767,-1.905) 6(2.767,-0.635) 7(2.767,0.635) 8(2.767,1.905)
SSOP_28_413X220_26
  rect 1.778x0.406 smd: 1(-3.625,4.225) 2(-3.625,3.575) 3(-3.625,2.925) 4(-3.625,2.275) 5(-3.625,1.625) 6(-3.625,0.975) 7(-3.625,0.325) 8(-3.625,-0.325) 9(-3.625,-0.975) 10(-3.625,-1.625) 11(-3.625,-2.275) 12(-3.625,-2.925) 13(-3.625,-3.575) 14(-3.625,-4.225) 15(3.625,-4.225) 16(3.625,-3.575) 17(3.625,-2.925) 18(3.625,-2.275) 19(3.625,-1.625) 20(3.625,-0.975) 21(3.625,-0.325) 22(3.625,0.325) 23(3.625,0.975) 24(3.625,1.625) 25(3.625,2.275) 26(3.625,2.925) 27(3.625,3.575) 28(3.625,4.225)
SW_SMVT_SPST_EVQPJX_2
  rect 2.007x1.6 smd: 1(-2.7,0) 2(2.7,0)
TANT_B
  rect 1.6x2.413 smd: 1(-1.867,0) 2(1.867,0)
TESTPOINT_62DIA
  round 2.337 hole 1.575: 1(0,0)
TESTPOINT_62DRILL_THM
  round 2.337 hole 1.575: 1(0,0)
TFMR_6_150X150_60
  rect 1.143x0.762 smd: 1(-1.524,1.524) 2(-1.524,0) 3(-1.524,-1.524) 4(1.524,-1.524) 5(1.524,0) 6(1.524,1.524)
TFMR_6_160X150_50
  rect 1.651x0.762 smd: 1(1.587,1.27) 2(1.587,0) 3(1.587,-1.27) 4(-1.587,-1.27) 5(-1.587,0) 6(-1.587,1.27)
TQFP_100_551X551_20
  rect 1.778x0.33 smd: 1(-7.7,6) 2(-7.7,5.5) 3(-7.7,5) 4(-7.7,4.5) 5(-7.7,4) 6(-7.7,3.5) 7(-7.7,3) 8(-7.7,2.5) 9(-7.7,2) 10(-7.7,1.5) 11(-7.7,1) 12(-7.7,0.5) 13(-7.7,0) 14(-7.7,-0.5) 15(-7.7,-1) 16(-7.7,-1.5) 17(-7.7,-2) 18(-7.7,-2.5) 19(-7.7,-3) 20(-7.7,-3.5) 21(-7.7,-4) 22(-7.7,-4.5) 23(-7.7,-5) 24(-7.7,-5.5) 25(-7.7,-6) 51(7.7,-6) 52(7.7,-5.5) 53(7.7,-5) 54(7.7,-4.5) 55(7.7,-4) 56(7.7,-3.5) 57(7.7,-3) 58(7.7,-2.5) 59(7.7,-2) 60(7.7,-1.5) 61(7.7,-1) 62(7.7,-0.5) 63(7.7,0) 64(7.7,0.5) 65(7.7,1) 66(7.7,1.5) 67(7.7,2) 68(7.7,2.5) 69(7.7,3) 70(7.7,3.5) 71(7.7,4) 72(7.7,4.5) 73(7.7,5) 74(7.7,5.5) 75(7.7,6)
  rect 0.33x1.778 smd: 26(-6,-7.7) 27(-5.5,-7.7) 28(-5,-7.7) 29(-4.5,-7.7) 30(-4,-7.7) 31(-3.5,-7.7) 32(-3,-7.7) 33(-2.5,-7.7) 34(-2,-7.7) 35(-1.5,-7.7) 36(-1,-7.7) 37(-0.5,-7.7) 38(0,-7.7) 39(0.5,-7.7) 40(1,-7.7) 41(1.5,-7.7) 42(2,-7.7) 43(2.5,-7.7) 44(3,-7.7) 45(3.5,-7.7) 46(4,-7.7) 47(4.5,-7.7) 48(5,-7.7) 49(5.5,-7.7) 50(6,-7.7) 76(6,7.7) 77(5.5,7.7) 78(5,7.7) 79(4.5,7.7) 80(4,7.7) 81(3.5,7.7) 82(3,7.7) 83(2.5,7.7) 84(2,7.7) 85(1.5,7.7) 86(1,7.7) 87(0.5,7.7) 88(0,7.7) 89(-0.5,7.7) 90(-1,7.7) 91(-1.5,7.7) 92(-2,7.7) 93(-2.5,7.7) 94(-3,7.7) 95(-3.5,7.7) 96(-4,7.7) 97(-4.5,7.7) 98(-5,7.7) 99(-5.5,7.7) 100(-6,7.7)
unnamed#2
  round 2.54 hole 3.175 unplated: (0,0)
unnamed#3
  round 1.016 smd: 1(0,0)
VCXO_6_CUSTOM
  rect 5.74x1.956 smd: 1(-3.81,2.54) 2(-3.81,0) 3(-3.81,-2.54) 4(3.81,-2.54) 5(3.81,0) 6(3.81,2.54)

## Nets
5.0V_IN: F1.1 J14.1 Q1.5(D5) Q1.6(D6) Q1.7(D7) Q1.8(D8) TP23.1(TP) U12.5(VIN)
5VIN: C103.1 C104.1 C118.1 C119.1 C120.1 C149.1 C194.1 F1.2 L2.1 Q1.1(S1) Q1.2(S2) Q1.3(S3) R41.1 R96.1 R112.1 R118.2 TP16.1(TP) U6.13(EN) U6.15(IN2) U6.16(IN1) U8.1(VIN2) U8.2(VIN3) U8.16(VIN1)
+2.5V: C96.2 C97.2 C105.1 C125.2 C126.1 C185.1 C288.1 C289.1 L1.2 R115.2 R125.1 R161.1 R166.1 R177.1 R187.1 R188.1 TP18.1(TP) U2.7(IN2) U2.8(IN1) U9.5(IN1) U9.6(IN2) U9.7(IN3) U9.8(IN4) U10.7(IN2) U10.8(IN1) U11.7(IN2) U11.8(IN1) U16.7(IN2) U16.8(IN1)
+3.3VCLK: C56.1 C61.1 C62.1 C63.1 C64.1 C75.1 C77.1 C78.1 C83.1 C152.2 C153.2 C154.2 FB1.1 FB2.1 FB5.1 FB6.1 FB7.1 FB8.1 FB9.1 FB16.2 JP2.2 R73.1 R78.1 R134.1 SJP1.1(PIN1) TP1.1(TP) U3.59(VCCIO2#59) U3.80(VCCIO2#80) U3.94(VCCIO2#94)
AVDD1.9V: C23.1 C24.1 C25.1 C26.1 C110.1 C111.1 C112.1 C113.1 C160.1 C161.1 FB15.2 JP7.1(PIN1) R18.1 R19.1 R23.1 R183.2 TP19.1(TP) U1.10(AVDD19V#10) U1.16(AVDD19V#16) U1.24(AVDD19V#24) U1.31(AVDD19V#31) U1.39(AVDD19V#39) U1.45(AVDD19V#45)
AVDD1.15V: C20.1 C21.1 C35.1 C36.1 C37.1 C38.1 C39.1 C40.1 C41.1 C130.1 C131.1 C132.1 C133.1 C171.1 C172.1 C291.1 C292.1 FB13.3 TP15.1(TP) U1.9(AVDD#9) U1.12(AVDD#12) U1.15(AVDD#15) U1.17(AVDD#17) U1.20(AVDD#20) U1.25(AVDD#25) U1.30(AVDD#30) U1.35(AVDD#35) U1.38(AVDD#38) U1.40(AVDD#40) U1.43(AVDD#43) U1.44(AVDD#44) U1.46(AVDD#46)
GND: C2.2 C4.1 C5.1 C8.2 C10.1 C11.1 C16.2 C17.2 C18.2 C19.2 C20.2 C21.2 C22.2 C23.2 C24.2 C25.2 C26.2 C35.2 C36.2 C37.2 C38.2 C39.2 C40.2 C41.2 C49.2 C50.2 C51.2 C52.2 C53.2 C56.2 C57.2 C58.2 C59.2 C60.2 C61.2 C62.2 C63.2 C64.2 C69.2 C74.2 C75.2 C76.2 C77.2 C78.2 C79.1 C81.1 C83.2 C84.1 C85.1 C87.2 C88.2 C90.1 C91.2 C93.2 C94.1 C95.2 C96.1 C97.1 C98.2 C99.2 C100.2 C101.2 C102.2 C103.2 C104.2 C105.2 C107.2 C108.2 C109.2 C110.2 C111.2 C112.2 C113.2 C114.2 C115.2 C116.2 C117.2 C118.2 C119.2 C120.2 C121.1 C123.2 C125.1 C126.2 C127.2 C128.2 C130.2 C131.2 C132.2 C133.2 C134.2 C135.2 C136.2 C138.2 C139.2 C142.2 C143.2 C144.2 C145.2 C146.2 C147.2 C148.2 C149.2 C150.2 C151.2 C152.1 C153.1 C154.1 C155.1 C156.1 C160.2 C161.2 C162.1 C163.2 C164.2 C165.1 C166.1 C170.2 C171.2 C172.2 C173.2 C174.2 C182.2 C183.2 C184.2 C185.2 C194.2 C195.2 C197.2 C198.2 C200.1 C201.2 C204.1 C205.1 C206.2 C263.2 C265.2 C271.2 C272.2 C273.2 C277.1 C278.2 C279.2 C280.2 C281.2 C282.2 C283.2 C284.2 C285.2 C286.2 C288.2 C289.2 C290.2 C291.2 C292.2 D1.2(CATHODE) D2.2(CATHODE) D3.2(CATHODE) D4.2(CATHODE) D5.2(CATHODE) D6.2(CATHODE) FB13.2 FB14.2 FB17.2 J1.2(SHIELD2) J1.3(SHIELD3) J1.4(SHIELD4) J1.5(SHIELD1) J3.A1 J3.A4 J3.A5 J3.A8 J3.A9 J3.A12 J3.A13 J3.A16 J3.A17 J3.A20 J3.A21 J3.A24 J3.A25 J3.A28 J3.A29 J3.A32 J3.A33 J3.A36 J3.A37 J3.A40 J3.B2 J3.B3 J3.B6 J3.B7 J3.B10 J3.B11 J3.B14 J3.B15 J3.B18 J3.B19 J3.B22 J3.B23 J3.B26 J3.B27 J3.B30 J3.B31 J3.B34 J3.B35 J3.B38 J3.B39 J3.C1 J3.C4 J3.C5 J3.C8 J3.C9 J3.C12 J3.C13 J3.C16 J3.C17 J3.C20 J3.C21 J3.C24 J3.C25 J3.C28 J3.C29 J3.C32 J3.C33 J3.C36 J3.C38 J3.C40 J3.D2 J3.D3 J3.D6 J3.D7 J3.D10 J3.D13 J3.D16 J3.D19 J3.D22 J3.D25 J3.D28 J3.D37 J3.D39 J3.E1 J3.E4 J3.E5 J3.E8 J3.E11 J3.E14 J3.E17 J3.E20 J3.E23 J3.E26 J3.E29 J3.E32 J3.E35 J3.E38 J3.E40 J3.F2 J3.F3 J3.F6 J3.F9 J3.F12 J3.F15 J3.F18 J3.F21 J3.F24 J3.F27 J3.F30 J3.F33 J3.F36 J3.F39 J3.G1 J3.G4 J3.G5 J3.G8 J3.G11 J3.G14 J3.G17 J3.G20 J3.G23 J3.G26 J3.G29 J3.G32 J3.G35 J3.G38 J3.G40 J3.H3 J3.H6 J3.H9 J3.H12 J3.H15 J3.H18 J3.H21 J3.H24 J3.H27 J3.H30 J3.H33 J3.H36 J3.H39 J3.J1 J3.J4 J3.J5 J3.J8 J3.J11 J3.J14 J3.J17 J3.J20 J3.J23 J3.J26 J3.J29 J3.J32 J3.J35 J3.J38 J3.J40 J3.K2 J3.K3 J3.K6 J3.K9 J3.K12 J3.K15 J3.K18 J3.K21 J3.K24 J3.K27 J3.K30 J3.K33 J3.K36 J3.K39 J5.2(SHIELD2) J5.3(SHIELD3) J5.4(SHIELD4) J5.5(SHIELD1) J6.2(SHIELD2) J6.3(SHIELD3) J6.4(SHIELD4) J6.5(SHIELD1) J10.2(SHIELD1) J12.2(GND#2) J12.3(GND#3) J12.4(GND#4) J12.5(GND#5) J13.5(GND) J13.6(GND1) J13.7(GND2) J13.8(GND3) J13.9(GND4) J14.2 J14.3 J15.2 J15.10 J17.2(SHIELD2) J17.3(SHIELD3) J17.4(SHIELD4) J17.5(SHIELD1) J18.2(SHIELD2) J18.3(SHIELD3) J18.4(SHIELD4) J18.5(SHIELD1) J21.2 J22.2 J23.2 J24.2 JP3.3(PIN3) JP7.3(PIN3) MT1.1 MT2.1 MT3.1 MT4.1 MT5.1 MT6.1 R13.1 R20.2 R21.2 R29.2 R32.2 R36.2 R40.2 R43.2 R44.2 R48.2 R51.2 R57.2 R59.2 R65.2 R66.2 R72.1 R74.2 R75.1 R76.1 R77.2 R79.2 R80.2 R83.1 R84.2 R87.2 R100.2 R102.2 R104.2 R105.2 R106.2 R114.2 R116.2 R117.2 R124.2 R126.2 R128.2 R162.2 R167.2 R170.2 R173.2 R178.2 R181.2 R184.1 R189.2 SJP1.3(PIN3) T1.6(PRIMARY_CT) T3.6(PRIMARY_CT) T6.6(PRIMARY_CT) T8.6(PRIMARY_CT) TP7.1(TP) TP8.1(TP) TP9.1(TP) TP10.1(TP) TP11.1(TP) TP24.1(TP) TP25.1(TP) TP26.1(TP) TP27.1(TP) U1.3(DGND#3) U1.21(AGND#21) U1.26(AGND#26) U1.29(AGND#29) U1.32(AGND#32) U1.52(DGND#52) U1.60(DGND#60) U1.63(DGND#63) U1.67(DGND#67) U1.73(PAD) U2.4(GND) U2.9(PAD) U3.1(GND#1) U3.10(GND#10) U3.11(GND#11) U3.32(GND#32) U3.46(GND#46) U3.60(GND#60) U3.65(GND#65) U3.79(GND#79) U3.93(GND#93) U5.65(DAP) U6.7(GND) U6.21(PWRPAD) U7.7(GND#7) U7.18(GND#18) U7.21(GND#21) U7.25(AGND) U7.26(TEST) U8.3(GND1) U8.4(GND2) U8.5(AGND) U8.17(PWRPAD) U9.2(NC1) U9.3(NC2) U9.4(NC3) U9.12(GND) U9.13(NC4) U9.14(NC5) U9.17(NC6) U9.21(PWRPAD) U10.4(GND) U10.9(PAD) U11.4(GND) U11.9(PAD) U12.2(GND) U15.5(GND) U16.4(GND) U16.9(PAD) Y1.3(GND)
VCC1_VCC5_VCC6: C50.1 C51.1 C52.1 FB1.2 U5.10(VCC1_VCO) U5.33(VCC5_DIG) U5.36(VCC6_PLL1)
VCC2_CG1: C174.1 FB5.2 U5.17(VCC2_GC1)
VCC3_SYSREF: C173.1 FB6.2 U5.21(VCC3_SYSREF)
VCC4_CG2: C102.1 FB7.2 U5.26(VCC4_CG2)
VCC7_OSCOUT: FB3.2 U5.39(VCC7_OSCOUT)
VCC8_OSCIN: FB11.2 U5.42(VCC8_OSCIN)
VCC8_VCC10: C57.1 C58.1 C59.1 FB2.2 FB3.1 FB4.1 FB11.1 U5.47(VCC10_PLL2)
VCC9_CP2: C164.1 FB4.2 U5.45(VCC9_CP2)
VCC11_CG3: C101.1 FB8.2 U5.53(VCC11_CG3)
VCC12_CG0: C100.1 FB9.2 U5.64(VCC12_CG0)
AAINM: T1.3(SECONDARY_DOT) T2.1(SECONDARY_CT)
AAINP: T1.1(SECONDARY_CT) T2.3(SECONDARY_DOT)
ACLK_N: C48.1 C193.2 R34.2 R39.2 U1.28(CLKIN_M)
ACLK_P: C47.1 C192.2 R34.1 R35.2 U1.27(CLKIN_P)
ACLKN: R39.1 T5.3(SECONDARY)
ACLKP: R35.1 T5.4(SECONDARY_DOT)
ADC_CLK: C43.1 J6.1(CENTER)
ADC_SCLK: J25.1 U1.6(SCLK) U3.33(IO_1_33/DIFFIO_B3N)
ADC_SDIO: J25.3 U1.5(SDIN) U3.35(IO_1_35/DIFFIO_B4N)
ADC_SDO: J25.4 U1.11(SDOUT) U3.36(IO_1_36/DIFFIO_B5P)
ADC_SEN: J25.2 R23.2 U1.7(SEN) U3.34(IO_1_34/DIFFIO_B4P)
ADCCLK: C43.2 T5.6(PRIMARY_DOT)
AIN+: J1.1(CENTER) T1.4(PRIMARY_DOT)
AINM: R6.2 R63.1 U1.41(INA_M)
AINP: R2.2 R101.2 U1.42(INA_P)
BBINM: T6.3(SECONDARY_DOT) T7.1(SECONDARY_CT)
BBINP: T6.1(SECONDARY_CT) T7.3(SECONDARY_DOT)
BIN: J17.1(CENTER) T6.4(PRIMARY_DOT)
BINM: R142.2 R146.2 U1.37(INB_M)
BINP: R141.2 R145.1 U1.36(INB_P)
CCINM: T8.1(SECONDARY_CT) T9.3(SECONDARY_DOT)
CCINP: T8.3(SECONDARY_DOT) T9.1(SECONDARY_CT)
CIN: J18.1(CENTER) T8.4(PRIMARY_DOT)
CINM: R153.2 R157.1 U1.18(INC_M)
CINP: R154.2 R158.2 U1.19(INC_P)
CLK_IN: C122.1 R62.2 R100.1
CLK_LAO_0M: C86.1 J3.G7
CLK_LAO_0P: C89.1 J3.G6
CLK_N: C71.1 R40.1 U5.16(DCLKOUT2N)
CLK_P: C70.1 R21.1 U5.15(DCLKOUT2P)
CLKIN: J12.1(CENTER) R60.1 R62.1
CLKIN1N: C79.2 C175.2 U5.35(CLKIN1N/FBCLKINN/FINN)
CLKIN1P: C122.2 U5.34(CLKIN1P/FBCLKINP/FINP)
CLKLA_0N: C89.2 R80.1 U5.63(DCLKOUT12N)
CLKLA_0P: C86.2 R79.1 U5.62(DCLKOUT12P)
CLKM: C48.2 C70.2
CLKP: C47.2 C71.2
CP1: C60.1 C65.1 C94.2 U5.32(CPOUT1) Y1.1(VC)
CP2: C66.1 C69.1 U5.46(CPOUT2)
DA_M: C28.1 U1.59(DAM)
DA_P: C27.1 U1.58(DAP)
DAM: C28.2 J3.A11
DAP: C27.2 J3.A10
DB_M: C30.1 U1.62(DBM)
DB_P: C29.1 U1.61(DBP)
DBM: C30.2 J3.A7
DBP: C29.2 J3.A6
DC_M: C32.1 U1.65(DCM)
DC_P: C31.1 U1.66(DCP)
DCM: C32.2 J3.A3
DCP: C31.2 J3.A2
DD_M: C34.1 U1.68(DDM)
DD_P: C33.1 U1.69(DDP)
DDINM: T3.1(SECONDARY_CT) T4.3(SECONDARY_DOT)
DDINP: T3.3(SECONDARY_DOT) T4.1(SECONDARY_CT)
DDM: C34.2 J3.C7
DDP: C33.2 J3.C6
DIN: J5.1(CENTER) T3.4(PRIMARY_DOT)
DINM: R8.2 R119.2 U1.14(IND_M)
DINP: R12.2 R107.1 U1.13(IND_P)
DRVDD1.15V: C16.1 C17.1 C142.1 C143.1 C145.1 C146.1 C147.1 FB14.3 TP14.1(TP) U1.8(DVDD#8) U1.47(DVDD#47)
FMC_CLK_N: C193.1 J3.K29
FMC_CLK_P: C192.1 J3.K28
FMC_D5: J3.G16 U3.7(IO_1_7/DIFFIO_L3N)
FMC_D6: J3.H16 U3.8(IO_1_8)
